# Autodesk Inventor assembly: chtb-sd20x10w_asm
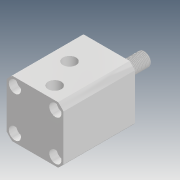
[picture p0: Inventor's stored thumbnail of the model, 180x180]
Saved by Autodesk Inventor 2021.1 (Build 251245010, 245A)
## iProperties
Company: Microsoft
Created: 2018-05
Part Number: chtb-sd20x10w_asm
Description: STEP AP214
Document SubType Name: Assembly
Designer: user
Title: chtb-sd20x10w_asm.STEP
Author: Windows
Revision Number: ÈÎºÎ
Sending System: SolidWorks 2015
Preprocessor: SwSTEP 2.0
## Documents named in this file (4)
- D:\Vault_2016\Projekty\Clamptek\Hydraulic\CHTB\CHTB-20\Inventor\CHTB-SD20x10W\chtb-sd20x10w_asm.iam
- D:\Vault_2016\Projekty\Clamptek\Hydraulic\CHTB\CHTB-20\Inventor\CHTB-SD20x10W\CHTB-SD20X10NBT.ipt
- D:\Vault_2016\Projekty\Clamptek\Hydraulic\CHTB\CHTB-20\Inventor\CHTB-SD20x10W\CHTB-SD20X10WHSG.ipt
- D:\Vault_2016\Projekty\Clamptek\Hydraulic\CHTB\CHTB-20\Inventor\CHTB-SD20x10W\QG.ipt
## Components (3 placed, 3 different names)
1. CHTB-SD20X10NBT_1
2. CHTB-SD20X10WHSG_2
3. QG_3
